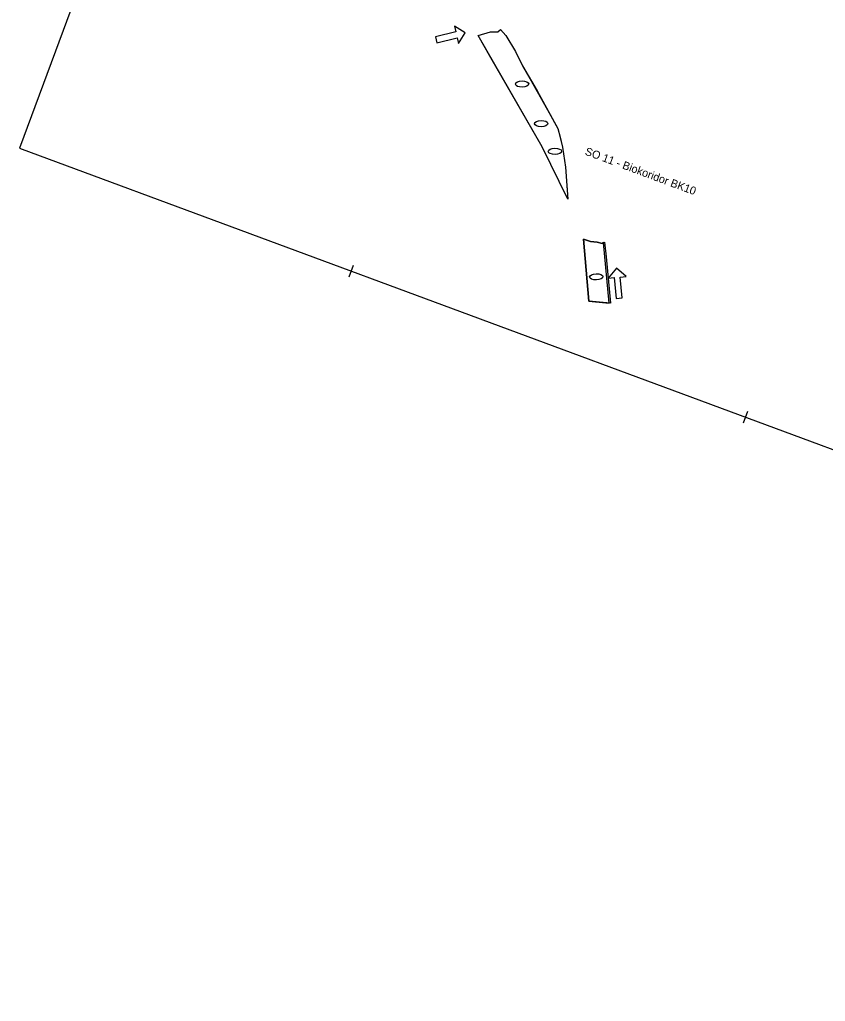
# Model space of a CAD drawing. Extents: x -552278 to -547230, y -1151007 to -1148251.
# Drawn here: x -551013 to -550209, y -1151001 to -1150020 of the extents above; entities that cross this region are included whole.
import ezdxf

# ---------------------------------------------------------------- set-up
doc = ezdxf.new("R2010")
doc.units = 0
for name, color, linetype in [('prijezdy', 7, 'Continuous'), ('u_BK10_srafa', 7, 'Continuous'), ('u_parcely dotčené stavbou', 7, 'Continuous'), ('u_popis', 7, 'Continuous'), ('u_STAVENIŠTĚ', 7, 'Continuous'), ('x_formát_křížky', 7, 'Continuous'), ('x_formát_rám', 7, 'Continuous')]:
    doc.layers.add(name, color=color, linetype=linetype)

msp = doc.modelspace()

# ---------------------------------------------------------------- linework, layer by layer
at = {"layer": 'prijezdy'}
for points in [[(-550574.88, -1150044.17), (-550568.28, -1150033.29), (-550579.15, -1150026.69), (-550577.73, -1150032.52), (-550598.13, -1150037.5), (-550596.71, -1150043.33), (-550576.31, -1150038.34), (-550574.88, -1150044.17)], [(-550407.5, -1150276.9), (-550417.25, -1150268.72), (-550425.43, -1150278.47), (-550419.46, -1150277.95), (-550417.63, -1150298.87), (-550411.65, -1150298.35), (-550413.48, -1150277.43), (-550407.5, -1150276.9)]]:
    msp.add_lwpolyline(points, dxfattribs=at)
at = {"layer": 'u_BK10_srafa'}
for points in [[(-550555.54, -1150036.23), (-550543.03, -1150032.38), (-550535.77, -1150032.44), (-550532.98, -1150030.01), (-550527.87, -1150035.93), (-550517.95, -1150051.96), (-550511.14, -1150066.39), (-550496.57, -1150091.44), (-550475.88, -1150128.95), (-550471.19, -1150147.78), (-550468.08, -1150167.57), (-550467.23, -1150181.76), (-550466.52, -1150190.68), (-550465.8, -1150199.59), (-550491.51, -1150147.38), (-550542.65, -1150058.53)], [(-550430.09, -1150243.03), (-550431.6, -1150243.76), (-550436.57, -1150242.74), (-550443.29, -1150242.04), (-550450.34, -1150239.65), (-550444.71, -1150301.43), (-550424.46, -1150303.39)]]:
    msp.add_lwpolyline(points, close=True, dxfattribs=at)
at = {"layer": 'u_parcely dotčené stavbou'}
for centre in [(-550511.47, -1150084.57), (-550492.46, -1150124.11), (-550478.7, -1150151.83), (-550437.38, -1150277.19)]:
    msp.add_ellipse(centre, major_axis=(-6.66, -0.17), ratio=0.464088, dxfattribs=at)
at = {"layer": 'u_STAVENIŠTĚ'}
msp.add_lwpolyline([(-550555.54, -1150036.23), (-550543.03, -1150032.38), (-550535.77, -1150032.44), (-550532.98, -1150030.01), (-550527.87, -1150035.93), (-550517.95, -1150051.96), (-550511.14, -1150066.39), (-550503.85, -1150078.92), (-550486.22, -1150110.2), (-550475.88, -1150128.95), (-550473.65, -1150137.52), (-550471.19, -1150147.78), (-550468.08, -1150167.57), (-550465.8, -1150199.59), (-550491.51, -1150147.38)], close=True, dxfattribs=at)
for points in [[(-550423.15, -1150303.51), (-550444.71, -1150301.43), (-550450.34, -1150239.65), (-550443.29, -1150242.04), (-550436.57, -1150242.74), (-550431.6, -1150243.76), (-550429.05, -1150242.52)], [(-550429.05, -1150242.52), (-550427.62, -1150257.33), (-550423.15, -1150303.51)]]:
    msp.add_lwpolyline(points, dxfattribs=at)
at = {"layer": 'x_formát_křížky'}
for p, q in [((-550684.29, -1150277.26), (-550679.94, -1150265.53)), ((-550290.46, -1150423.21), (-550286.12, -1150411.49))]:
    msp.add_line(p, q, dxfattribs=at)
at = {"layer": 'x_formát_rám'}
msp.add_lwpolyline([(-551013.31, -1150148.65), (-548712.99, -1151001.15), (-548408.91, -1150180.65), (-550709.24, -1149328.16)], close=True, dxfattribs=at)

# ---------------------------------------------------------------- texts
at = {"layer": 'u_popis'}
msp.add_text('SO 11 - Biokoridor BK10', height=8, rotation=339.66537, dxfattribs=at).set_placement((-550449.4, -1150154.99))

doc.saveas('drawing.dxf')
